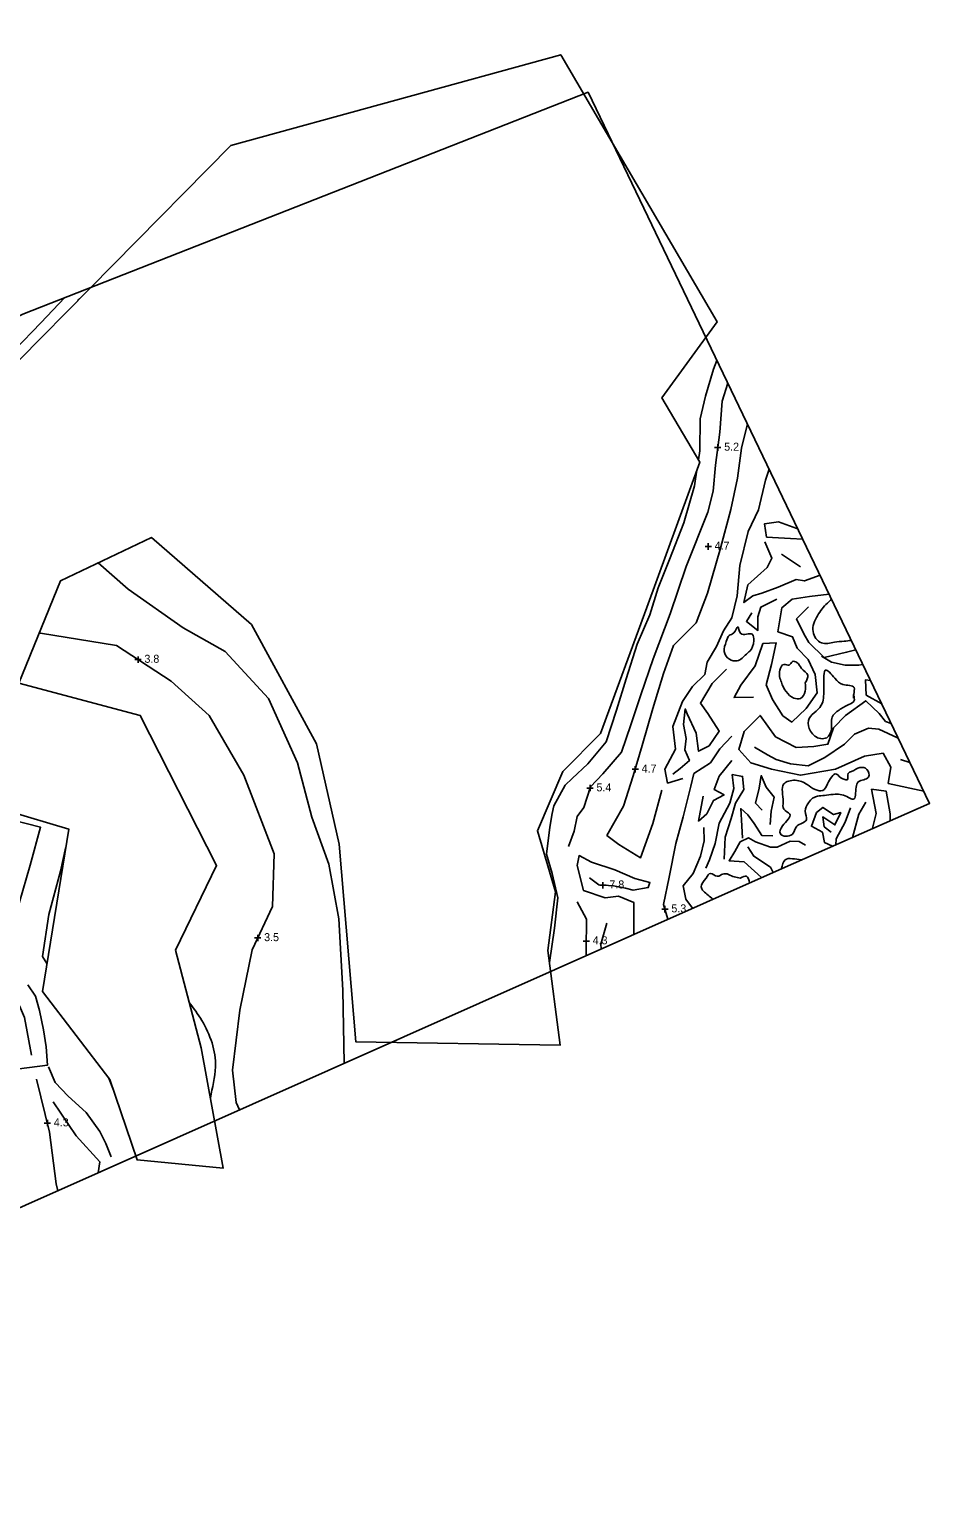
# Model space of a CAD drawing. Extents: x 2316231 to 2323598, y 363169 to 371906.
# Drawn here: x 2323036 to 2323598, y 368746 to 369666 of the extents above; entities that cross this region are included whole.
import ezdxf

# ---------------------------------------------------------------- set-up
doc = ezdxf.new("R2010")
doc.units = 0
for name, color, linetype in [('RD_DTM_BkLn1', 7, 'Continuous'), ('RD_DTM_Holes', 7, 'Continuous'), ('RD_DTM_TinHull', 7, 'Continuous'), ('RD_DTM_Void', 7, 'Continuous'), ('RD_EX_H2O', 7, 'Continuous'), ('RD_EX_Road', 7, 'Continuous')]:
    doc.layers.add(name, color=color, linetype=linetype)

msp = doc.modelspace()

# ---------------------------------------------------------------- linework, layer by layer
at = {"layer": 'RD_DTM_BkLn1'}
for p, q in [((2323505.558, 369338.099), (2323517.393, 369330.109)), ((2323580.004, 369209.738), (2323585.796, 369208.044)), ((2323060.157, 369166.073), (2323060.018, 369166.309))]:
    msp.add_line(p, q, dxfattribs=at)
for points in [[(2323398.933, 369597.048), (2323398.643, 369597.08), (2323398.642, 369597.08)], [(2323065.774, 369496.577), (2323066.082, 369496.949), (2323066.929, 369497.747)], [(2323453.643, 369396.96), (2323454.503, 369402.698), (2323454.756, 369422.653), (2323458.001, 369436.74), (2323463.016, 369453.63), (2323465.241, 369459.011)], [(2323372.487, 369155.383), (2323376.097, 369164.976), (2323377.912, 369174.108), (2323381.965, 369179.852), (2323386.227, 369192.807), (2323393.932, 369200.811), (2323405.557, 369214.416), (2323411.468, 369231.417), (2323417.682, 369250.243), (2323425.447, 369272.757), (2323436.021, 369300.883), (2323445.987, 369330.376), (2323459.588, 369364.302), (2323462.909, 369377.529), (2323464.31, 369393.687), (2323467.018, 369414.313), (2323468.507, 369433.647), (2323472.066, 369444.803)], [(2323430.732, 369190.707), (2323425.072, 369169.798), (2323417.533, 369148.464), (2323403.969, 369156.697), (2323396.496, 369162.378), (2323406.886, 369180.653), (2323412.934, 369199.611), (2323418.6, 369218.514), (2323425.201, 369241.743), (2323431.741, 369263.635), (2323438.003, 369281.075), (2323452.295, 369295.122), (2323459.295, 369313.642), (2323467.41, 369341.861), (2323473.972, 369366.047), (2323477.983, 369385.609), (2323480.495, 369404.385), (2323484.252, 369419.435)], [(2323360.572, 369083.102), (2323363.771, 369104.405), (2323365.688, 369123.473), (2323362.17, 369138.529), (2323358.649, 369150.672), (2323360.856, 369167.479), (2323362.308, 369176.065), (2323363.2, 369180.918), (2323370.279, 369193.717), (2323374.845, 369197.999), (2323384.541, 369207.059), (2323396.073, 369220.916), (2323402.557, 369240.551), (2323408.528, 369260.203), (2323415.39, 369281.866), (2323423.308, 369300.27), (2323428.585, 369317.145), (2323435.624, 369334.698), (2323444.539, 369357.667), (2323451.223, 369380.8), (2323452.714, 369390.754)], [(2323443.971, 369197.884), (2323434.403, 369195.045), (2323432.702, 369203.755), (2323439.253, 369216.296), (2323437.639, 369230.523), (2323443.739, 369245.993), (2323449.952, 369255.408), (2323457.616, 369262.97), (2323459.096, 369270.696), (2323464.893, 369280.365), (2323469.27, 369290.238), (2323474.514, 369298.204), (2323477.78, 369312.005), (2323479.564, 369330.907), (2323484.654, 369352.167), (2323491.12, 369365.783), (2323495.588, 369384.386), (2323497.867, 369391.09)], [(2323515.59, 369354.196), (2323515.127, 369354.135), (2323503.688, 369358.288), (2323494.934, 369357.006), (2323496.244, 369348.706), (2323511.249, 369347.96), (2323518.872, 369347.364)], [(2323529.656, 369324.913), (2323519.869, 369321.344), (2323514.838, 369322.25), (2323503.496, 369317.456), (2323493.275, 369313.763), (2323487.705, 369311.998), (2323482.125, 369307.797), (2323484.639, 369318.977), (2323496.572, 369329.653), (2323499.552, 369335.586), (2323495.226, 369345.813)], [(2323078.608, 369332.695), (2323097.152, 369316.133), (2323131.593, 369292.16), (2323157.793, 369277.327), (2323184.995, 369247.891), (2323203.011, 369207.741), (2323212.066, 369173.836), (2323222.632, 369144.503), (2323228.937, 369110.24), (2323231.435, 369065.717), (2323232.19, 369020.028)], [(2323535.315, 369313.133), (2323523.173, 369311.664), (2323512.229, 369309.912), (2323505.863, 369304.584), (2323503.362, 369289.641), (2323512.553, 369286.381), (2323515.391, 369279.309), (2323522.242, 369272.26), (2323526.696, 369262.939), (2323527.964, 369251.367), (2323521.068, 369241.696), (2323512.093, 369233.154), (2323506.408, 369237.111), (2323499.943, 369247.214), (2323495.93, 369256.399), (2323499.247, 369269.148), (2323502.259, 369282.617), (2323493.98, 369282.25), (2323489.112, 369268.381), (2323480.104, 369256.257), (2323475.985, 369248.507), (2323488.097, 369248.707)], [(2323502.736, 369310.07), (2323492.753, 369305.037), (2323490.858, 369298.904), (2323490.793, 369290.413), (2323483.618, 369296.019), (2323486.975, 369301.339)], [(2323522.481, 369305.161), (2323514.961, 369297.681), (2323519.558, 369288.372), (2323522.565, 369282.815), (2323532.179, 369273.591), (2323546.289, 369276.842), (2323552.04, 369278.316)], [(2323041.626, 369288.785), (2323042.49, 369288.802), (2323089.941, 369280.978), (2323124.136, 369258.775), (2323147.839, 369237.312), (2323169.535, 369199.984), (2323188.437, 369150.893), (2323187.528, 369117.95), (2323174.67, 369090.836), (2323167.114, 369053.14), (2323162.522, 369015.74), (2323164.858, 368995.523), (2323166.807, 368990.953)], [(2323530.574, 369274.394), (2323536.761, 369270.515), (2323545.333, 369268.825), (2323553.739, 369268.641), (2323556.426, 369269.186)], [(2323471.153, 369266.179), (2323462.331, 369257.374), (2323454.896, 369244.913), (2323459.58, 369238.6), (2323466.634, 369227.536), (2323460.388, 369218.385), (2323453.716, 369214.922), (2323452.148, 369226.366), (2323446.68, 369238.442), (2323445.442, 369241.428), (2323444.398, 369231.775), (2323446.074, 369222.946), (2323445.149, 369215.86), (2323448.038, 369209.11), (2323442.249, 369204.194), (2323437.595, 369200.749)], [(2323561.192, 369259.262), (2323558.076, 369259.561), (2323558.455, 369250.098), (2323568.205, 369244.664)], [(2323594.478, 369189.97), (2323572.345, 369194.83), (2323573.859, 369205.04), (2323569.041, 369213.731), (2323557.464, 369211.997), (2323539.403, 369203.824), (2323517.5, 369199.963), (2323499.429, 369203.794), (2323486.459, 369207.757), (2323478.83, 369215.972), (2323482.181, 369227.228), (2323492.245, 369237.3), (2323501.751, 369224.028), (2323514.684, 369217.294), (2323525.821, 369217.898), (2323534.564, 369219.335), (2323538.097, 369229.646), (2323545.501, 369237.401), (2323558.184, 369246.482), (2323566.675, 369238.558), (2323570.63, 369233.542), (2323574.102, 369232.387)], [(2323434.512, 369109.999), (2323431.922, 369119.276), (2323435.313, 369136.252), (2323439.471, 369157.425), (2323444.173, 369174.103), (2323448.861, 369193.17), (2323450.748, 369201.059), (2323461.163, 369207.736), (2323467.046, 369216.377), (2323474.464, 369224.372)], [(2323578.603, 369223.017), (2323578.037, 369223.263), (2323566.514, 369228.73), (2323559.926, 369229.292), (2323551.234, 369225.573), (2323544.944, 369219.444), (2323532.661, 369210.968), (2323522.153, 369205.94), (2323511.116, 369207.079), (2323502.266, 369209.715), (2323496.727, 369212.668), (2323488.674, 369217.554)], [(2323474.506, 369209.275), (2323466.714, 369199.493), (2323463.437, 369191.114), (2323469.663, 369187.642), (2323463.123, 369184.262), (2323458.855, 369175.869), (2323453.715, 369171.389), (2323456.686, 369186.9)], [(2323469.729, 369147.512), (2323470.271, 369161.23), (2323474.212, 369173.054), (2323476.903, 369182.596), (2323482.092, 369191.076), (2323481.306, 369199.229), (2323474.76, 369200.399), (2323475.852, 369191.778), (2323473.379, 369182.544), (2323466.553, 369169.959), (2323464.169, 369157.368), (2323460.684, 369147.153), (2323458.295, 369141.872)], [(2323498.446, 369169.167), (2323499.047, 369177.498), (2323501.037, 369186.258), (2323496.019, 369192.598), (2323492.968, 369199.804), (2323491.605, 369191.838), (2323489.382, 369182.447), (2323493.595, 369178.157)], [(2323573.509, 369171.556), (2323573.593, 369175.817), (2323571.07, 369189.957), (2323561.85, 369191.271), (2323564.723, 369176.185), (2323562.476, 369166.865), (2323562.459, 369166.684)], [(2323500.137, 369162.058), (2323493.391, 369162.238), (2323488.564, 369169.914), (2323484.623, 369175.24), (2323480.12, 369179.151), (2323480.774, 369168.325), (2323481.158, 369160.665)], [(2323537.479, 369155.669), (2323532.359, 369158.003), (2323531.294, 369164.366), (2323524.269, 369168.12), (2323527.452, 369176.607), (2323531.495, 369179.89), (2323538.083, 369175.447), (2323542.572, 369176.637), (2323538.955, 369168.966), (2323531.309, 369173.968), (2323532.22, 369167.773), (2323536.645, 369164.497)], [(2323548.654, 369179.579), (2323545.289, 369170.748), (2323539.712, 369160.289), (2323539.624, 369156.615)], [(2323549.863, 369161.129), (2323553.862, 369175.734), (2323558.205, 369183.075)], [(2323457.009, 369167.239), (2323457.161, 369159.02), (2323454.877, 369149.427), (2323450.466, 369138.551), (2323444.102, 369130.857), (2323445.866, 369122.589), (2323449.994, 369116.883)], [(2323520.603, 369156.342), (2323516.598, 369158.504), (2323510.975, 369158.699), (2323502.833, 369155.118), (2323498.616, 369155.073), (2323489.331, 369158.429), (2323484.934, 369160.858), (2323479.847, 369158.348), (2323476.353, 369152.373), (2323472.826, 369146.612), (2323482.314, 369145.857), (2323493.114, 369136.059)], [(2323046.492, 369082.346), (2323043.735, 369086.771), (2323047.772, 369113.093), (2323054.874, 369140.139), (2323058.401, 369155.318)], [(2323413.308, 369100.569), (2323413.348, 369105.793), (2323413.219, 369120.521), (2323403.771, 369124.369), (2323395.403, 369123.489), (2323381.9, 369127.983), (2323377.779, 369143.666), (2323379.065, 369149.829), (2323386.85, 369145.674), (2323401.485, 369140.931), (2323413.928, 369135.455), (2323423.34, 369132.921), (2323422.249, 369129.814), (2323412.967, 369128.286), (2323408.177, 369129.524), (2323400.665, 369130.834), (2323391.319, 369131.433), (2323385.614, 369135.88)], [(2323500.386, 369139.292), (2323498.658, 369142.603), (2323488.317, 369149.338), (2323484.478, 369155.309)], [(2323377.882, 369120.89), (2323383.661, 369110.172), (2323383.51, 369090.944), (2323383.51, 369087.319)], [(2323396.488, 369107.595), (2323392.739, 369094.503), (2323392.821, 369091.459)], [(2323009.112, 369074.999), (2323016.678, 369071.693), (2323025.956, 369063.595), (2323032.366, 369048.692), (2323036.892, 369025.063)], [(2323039.874, 369010.106), (2323048.173, 368977.104), (2323052.179, 368944.809), (2323053.241, 368940.451)], [(2323088.187, 369002.976), (2323088.038, 369003.267), (2323084.908, 369011.094)], [(2323078.599, 368951.727), (2323079.521, 368958.426), (2323064.8, 368974.695), (2323050.483, 368996.048)]]:
    msp.add_lwpolyline(points, dxfattribs=at)
at = {"layer": 'RD_DTM_Holes'}
for points in [[(2323022.464, 369177.458), (2323060.187, 369166.259), (2323043.644, 369064.892), (2323085.876, 369009.832), (2323102.786, 368959.66), (2323156.591, 368954.525), (2323142.822, 369029.606), (2323126.741, 369090.794), (2323152.553, 369143.599), (2323104.855, 369237.297), (2323028.937, 369257.526), (2323054.909, 369321.509), (2323111.908, 369348.412), (2323174.285, 369294.232), (2323214.871, 369219.648), (2323229.099, 369156.949), (2323239.526, 369033.54), (2323367.191, 369031.281), (2323359.62, 369090.552), (2323364.395, 369127.115), (2323353.025, 369165.222), (2323368.829, 369202.341), (2323392.477, 369226.012), (2323421.473, 369304.729), (2323454.462, 369395.568), (2323430.857, 369435.697), (2323465.326, 369483.133), (2323367.654, 369650.031), (2323161.358, 369593.396)], [(2323161.358, 369593.396), (2323014.032, 369444.167)]]:
    msp.add_lwpolyline(points, dxfattribs=at)
at = {"layer": 'RD_DTM_TinHull'}
msp.add_lwpolyline([(2319782.271, 371232.132), (2319735.05, 371773.026), (2320925.274, 371905.831), (2321343.399, 371858.015), (2321109.741, 371125.092), (2321259.088, 370783.878), (2321451.866, 370308.131), (2321545.882, 369878.312), (2321496.483, 369600.925), (2321592.742, 369376.322), (2321772.553, 369180.585), (2321930.831, 369046.826), (2322410.389, 369187.058), (2322700.489, 369322.074), (2323031.423, 369488.086), (2323384.71, 369626.658), (2323598.112, 369182.404), (2323506.079, 369141.824), (2322749.057, 368805.183), (2322437.788, 368637.943)], dxfattribs=at)
at = {"layer": 'RD_DTM_Void'}
for p, q in [((2323465.756, 369402.704), (2323465.756, 369406.704)), ((2323463.756, 369404.704), (2323467.756, 369404.704)), ((2323457.776, 369342.886), (2323461.776, 369342.886)), ((2323459.776, 369340.886), (2323459.776, 369344.886)), ((2323101.422, 369272.224), (2323105.422, 369272.224)), ((2323103.422, 369270.224), (2323103.422, 369274.224)), ((2323412.154, 369203.679), (2323416.154, 369203.679)), ((2323414.154, 369201.679), (2323414.154, 369205.679)), ((2323385.941, 369189.937), (2323385.941, 369193.937)), ((2323383.941, 369191.937), (2323387.941, 369191.937)), ((2323392.006, 369131.261), (2323396.006, 369131.261)), ((2323394.006, 369129.261), (2323394.006, 369133.261)), ((2323430.749, 369116.316), (2323434.749, 369116.316)), ((2323432.749, 369114.316), (2323432.749, 369118.316)), ((2323176.232, 369098.347), (2323180.232, 369098.347)), ((2323178.232, 369096.347), (2323178.232, 369100.347)), ((2323381.553, 369096.379), (2323385.553, 369096.379)), ((2323383.553, 369094.379), (2323383.553, 369098.379)), ((2323044.772, 368982.676), (2323048.772, 368982.676)), ((2323046.772, 368980.676), (2323046.772, 368984.676))]:
    msp.add_line(p, q, dxfattribs=at)
at = {"layer": 'RD_EX_H2O'}
for points in [[(2323536.918, 369309.796), (2323534.267, 369307.562), (2323528.08, 369299.604), (2323525.315, 369289.729), (2323530.553, 369282.67), (2323538.642, 369283.051), (2323544.74, 369283.724), (2323549.208, 369284.212)], [(2323483.637, 369275.692), (2323485.695, 369277.465), (2323488.24, 369284.082), (2323487.248, 369288.02), (2323480.053, 369288.707), (2323478.346, 369292.735), (2323475.73, 369288.842), (2323472.945, 369287.266), (2323471, 369283.427), (2323469.798, 369277.346), (2323473.097, 369272.456), (2323477.818, 369271.493), (2323483.637, 369275.692)], [(2323520.367, 369257.802), (2323522.022, 369262.492), (2323518.095, 369266.66), (2323515.226, 369270.413), (2323512.365, 369270.952), (2323510.35, 369268.713), (2323507.202, 369269.208), (2323504.553, 369265.601), (2323505.488, 369258.02), (2323513.352, 369248.191), (2323517.518, 369247.938), (2323520.426, 369252.486), (2323520.367, 369257.802)], [(2323550.483, 369248.057), (2323550.709, 369250.658), (2323550.985, 369254.717), (2323543.992, 369256.655), (2323538.856, 369260.548), (2323532.906, 369265.522), (2323532.011, 369260.407), (2323531.955, 369252.883), (2323530.462, 369243.653), (2323522.361, 369234.148), (2323523.735, 369227.59), (2323530.082, 369222.887), (2323533.813, 369223.438), (2323536.847, 369228.761), (2323537.249, 369236.174), (2323541.518, 369240.674), (2323547.629, 369244.154), (2323550.996, 369246.667), (2323550.648, 369249.951)], [(2323545.316, 369197.333), (2323543.814, 369197.681), (2323539.853, 369200.715), (2323534.411, 369194.614), (2323531.316, 369190.474), (2323526.627, 369190.994), (2323521.58, 369194.181), (2323514.163, 369196.804), (2323507.024, 369194.516), (2323506.636, 369183.365), (2323506.953, 369178.8), (2323510.735, 369175.708), (2323506.249, 369168.32), (2323504.901, 369163.292), (2323512.22, 369162.987), (2323515.097, 369168.096), (2323521.165, 369172.161), (2323520.401, 369177.447), (2323522.468, 369182.827), (2323525.026, 369185.622), (2323533.689, 369187.478), (2323539.094, 369188.146), (2323547.484, 369186.135), (2323550.327, 369184.95), (2323552.211, 369192.529), (2323553.555, 369195.765), (2323559.961, 369198.872), (2323559.012, 369203.575), (2323554.64, 369204.821), (2323549.387, 369202.396), (2323547.214, 369201.138), (2323546.82, 369197.26), (2323544.439, 369197.537)], [(2323518.267, 369147.198), (2323517.881, 369147.206), (2323507.824, 369147.094), (2323505.653, 369141.634)], [(2323479.845, 369135.788), (2323476.173, 369136.466), (2323468.832, 369138.276), (2323465.511, 369136.873), (2323461.216, 369138.692), (2323458.407, 369135.768), (2323455.408, 369130.349), (2323459.671, 369125.019), (2323462.719, 369122.542)], [(2323485.599, 369132.717), (2323483.701, 369136.839), (2323479.845, 369135.788)], [(2323148.597, 368998.115), (2323148.654, 368998.417), (2323151.863, 369017.76), (2323143.289, 369046.764), (2323135.347, 369058.047)]]:
    msp.add_spline(points, degree=3, dxfattribs=at)
at = {"layer": 'RD_EX_Road'}
for points in [[(2322833.582, 369220.749), (2322833.582, 369220.749), (2322840.855, 369233.904), (2322851.061, 369250.4), (2322858.216, 369260.976), (2322867.836, 369274.767), (2322878.601, 369289.634), (2322892.851, 369306.93), (2322905.019, 369322.489), (2322916.704, 369337.419), (2322928.149, 369350.966), (2322942.585, 369367.639), (2322959.006, 369387.232), (2322974.819, 369405.684), (2322988.343, 369421.971), (2322997.94, 369431.844), (2323011.309, 369448.109), (2323026.169, 369465.483), (2323042.59, 369482.544), (2323057.677, 369498.384)], [(2323029.181, 369120.105), (2323035.917, 369143.739), (2323042.486, 369167.447), (2323025.46, 369171.925)], [(2323029.16, 369016.665), (2323046.809, 369018.87), (2323045.945, 369030.343), (2323044.287, 369041.035), (2323041.816, 369053.049), (2323039.318, 369062.005), (2323034.474, 369069.131)], [(2323047.444, 369017.765), (2323051.714, 369008.028), (2323059.771, 368999.619), (2323071.084, 368989.4), (2323079.634, 368977.463), (2323083.376, 368969.916), (2323086.704, 368961.645)]]:
    msp.add_lwpolyline(points, dxfattribs=at)

# ---------------------------------------------------------------- texts
at = {"layer": 'RD_DTM_Void'}
for s, p in [('5.2', (2323469.756, 369402.704)), ('4.7', (2323463.776, 369340.886)), ('3.8', (2323107.422, 369270.224)), ('4.7', (2323418.154, 369201.679)), ('5.4', (2323389.941, 369189.937)), ('7.8', (2323398.006, 369129.261)), ('5.3', (2323436.749, 369114.316)), ('3.5', (2323182.232, 369096.347)), ('4.3', (2323387.553, 369094.379)), ('4.3', (2323050.772, 368980.676))]:
    msp.add_text(s, height=5, dxfattribs=at).set_placement(p)

doc.saveas('drawing.dxf')
